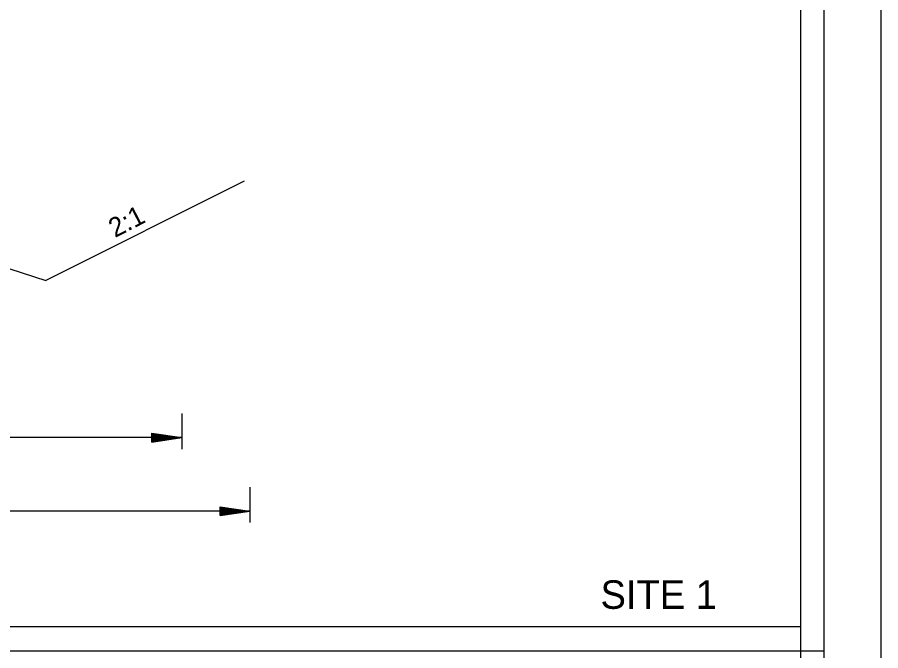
# Model space of a CAD drawing. Extents: x 1368648 to 1927880, y -1037443 to 380209.
# Drawn here: x 1373048.4 to 1373412.1, y 379219.6 to 379486.2 of the extents above; entities that cross this region are included whole.
import ezdxf

# ---------------------------------------------------------------- set-up
doc = ezdxf.new("R2010")
doc.units = 0
for name, color, linetype in [('R_Border', 7, 'Continuous'), ('R_Border Plan-Plan', 7, 'Continuous'), ('R_Border Title', 7, 'Continuous'), ('R_Dimension', 7, 'Continuous'), ('R_Fin Surface', 7, 'Continuous'), ('R_No Plot', 7, 'Continuous'), ('R_Xsect Slope', 7, 'Continuous')]:
    doc.layers.add(name, color=color, linetype=linetype)

msp = doc.modelspace()

# ---------------------------------------------------------------- linework, layer by layer
at = {"layer": 'R_Border'}
msp.add_line((1373388.3, 378705.96), (1373388.3, 379733.26), dxfattribs=at)
at = {"layer": 'R_Border Plan-Plan'}
msp.add_line((1371807.4, 379219.61), (1373388.3, 379219.61), dxfattribs=at)
at = {"layer": 'R_Dimension'}
for p, q in [((1373117.62, 379319.4), (1373117.62, 379306.93)), ((1373117.62, 379309.27), (1372650.7, 379309.27)), ((1373105.12, 379311.14), (1373117.62, 379309.27)), ((1373105.12, 379307.39), (1373105.12, 379311.14)), ((1373105.12, 379310.83), (1373115.53, 379309.27)), ((1373105.12, 379310.51), (1373113.38, 379309.27)), ((1373105.12, 379310.2), (1373111.3, 379309.27)), ((1373105.12, 379309.88), (1373109.18, 379309.27)), ((1373105.12, 379309.56), (1373107.09, 379309.27)), ((1373105.12, 379307.39), (1373117.62, 379309.27)), ((1373105.12, 379308.66), (1373109.18, 379309.27)), ((1373105.12, 379308.03), (1373113.38, 379309.27)), ((1373105.12, 379307.71), (1373115.53, 379309.27)), ((1373105.12, 379308.34), (1373111.3, 379309.27)), ((1373105.12, 379308.98), (1373107.09, 379309.27)), ((1373117.62, 379306.93), (1373117.62, 379304.47)), ((1373146.32, 379288.45), (1373146.32, 379275.99)), ((1373133.82, 379280.2), (1373146.32, 379278.33)), ((1373133.82, 379276.45), (1373133.82, 379280.2)), ((1373146.32, 379278.33), (1372767.04, 379278.33)), ((1373133.82, 379279.89), (1373144.24, 379278.33)), ((1373133.82, 379279.57), (1373142.09, 379278.33)), ((1373133.82, 379279.26), (1373140, 379278.33)), ((1373133.82, 379278.94), (1373137.89, 379278.33)), ((1373133.82, 379278.62), (1373135.8, 379278.33)), ((1373133.82, 379276.45), (1373146.32, 379278.33)), ((1373133.82, 379277.72), (1373137.89, 379278.33)), ((1373133.82, 379277.08), (1373142.09, 379278.33)), ((1373133.82, 379276.77), (1373144.24, 379278.33)), ((1373133.82, 379277.4), (1373140, 379278.33)), ((1373133.82, 379278.03), (1373135.8, 379278.33)), ((1373146.32, 379275.99), (1373146.32, 379273.53))]:
    msp.add_line(p, q, dxfattribs=at)
at = {"layer": 'R_Fin Surface'}
for p in [(1373143.92, 379417.17), (1372960.72, 379407.57)]:
    msp.add_line(p, (1373060.45, 379375.43), dxfattribs=at)
at = {"layer": 'R_No Plot'}
for points in [[(1371745.37, 379752.73), (1373412.07, 379752.73), (1373412.07, 378686.04), (1371745.37, 378686.04)], [(1373378.3, 379229.61), (1371817.4, 379229.61), (1371817.4, 379723.26), (1373065.1, 379723.26), (1373065.1, 379673.86), (1373152.8, 379673.86), (1373273.3, 379673.86), (1373273.3, 379562.19), (1373378.3, 379562.19)], [(1371817.4, 379723.26), (1373065.1, 379723.26), (1373065.1, 379673.86), (1373152.8, 379673.86), (1373273.3, 379673.86), (1373273.3, 379562.19), (1373378.3, 379562.19), (1373378.3, 378715.96), (1371817.4, 378715.96)]]:
    msp.add_lwpolyline(points, close=True, dxfattribs=at)

# ---------------------------------------------------------------- texts
at = {"layer": 'R_Border Title'}
msp.add_text('SITE 1', height=12, dxfattribs=at).set_placement((1373294.04, 379237.23))
at = {"layer": 'R_Xsect Slope'}
msp.add_text('2:1', height=8.125, rotation=27.1112, dxfattribs=at).set_placement((1373089.5, 379393.24))

doc.saveas('drawing.dxf')
